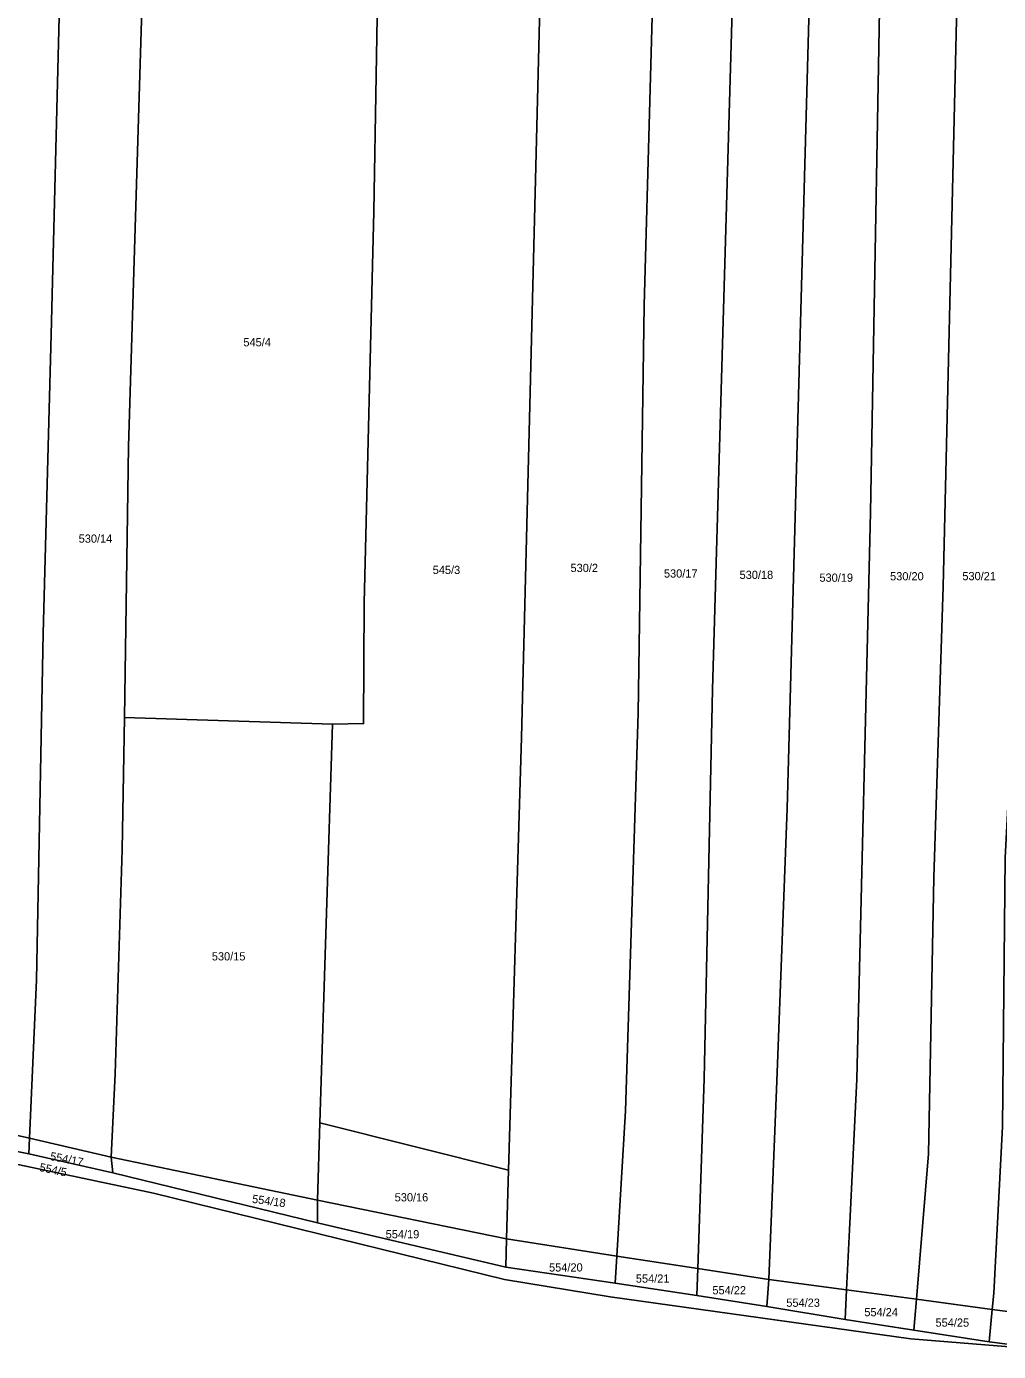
# Model space of a CAD drawing. Extents: x -747333 to -743907, y -1134120 to -1130051.
# Drawn here: x -746843.6 to -746642.5, y -1133009.1 to -1132734.9 of the extents above; entities that cross this region are included whole.
import ezdxf

# ---------------------------------------------------------------- set-up
doc = ezdxf.new("R2010")
doc.units = 0
doc.layers.add('Hranice parcel', color=7, linetype='Continuous')
doc.layers.add('Parcelní čísla', color=7, linetype='Continuous')

msp = doc.modelspace()

# ---------------------------------------------------------------- linework, layer by layer
at = {"layer": 'Hranice parcel'}
for p, q in [((-746780.29, -1132879.28), (-746823.3, -1132877.9)), ((-746782.89, -1132961.74), (-746780.29, -1132879.28)), ((-746859.24, -1132961.35), (-746843.01, -1132964.9)), ((-746783.4, -1132977.73), (-746782.89, -1132961.74)), ((-746743.9, -1132971.52), (-746782.89, -1132961.74)), ((-746843.15, -1132968.18), (-746859.32, -1132964.96)), ((-746843.15, -1132968.18), (-746843.01, -1132964.9)), ((-746843.01, -1132964.9), (-746826.09, -1132968.83)), ((-746825.76, -1132972.07), (-746843.15, -1132968.18)), ((-746825.76, -1132972.07), (-746826.09, -1132968.83)), ((-746826.09, -1132968.83), (-746783.4, -1132977.73)), ((-746783.4, -1132982.44), (-746825.76, -1132972.07)), ((-746743.9, -1132971.52), (-746744.27, -1132985.78)), ((-746783.4, -1132982.44), (-746783.4, -1132977.73)), ((-746783.4, -1132977.73), (-746744.27, -1132985.78)), ((-746744.46, -1132991.63), (-746783.4, -1132982.44)), ((-746744.46, -1132991.63), (-746744.27, -1132985.78)), ((-746744.27, -1132985.78), (-746721.44, -1132989.34)), ((-746721.78, -1132994.93), (-746721.44, -1132989.34)), ((-746721.44, -1132989.34), (-746704.71, -1132991.91)), ((-746721.78, -1132994.93), (-746744.46, -1132991.63)), ((-746704.9, -1132997.51), (-746704.71, -1132991.91)), ((-746704.71, -1132991.91), (-746690.04, -1132994.16)), ((-746704.9, -1132997.51), (-746721.78, -1132994.93)), ((-746690.41, -1132999.79), (-746690.04, -1132994.16)), ((-746690.04, -1132994.16), (-746673.93, -1132996.32)), ((-746690.41, -1132999.79), (-746704.9, -1132997.51)), ((-746674.21, -1133002.43), (-746673.93, -1132996.32)), ((-746673.93, -1132996.32), (-746659.48, -1132998.26)), ((-746674.21, -1133002.43), (-746690.41, -1132999.79)), ((-746660.01, -1133004.66), (-746659.48, -1132998.26)), ((-746659.48, -1132998.26), (-746643.78, -1133000.37)), ((-746644.4, -1133007.07), (-746643.78, -1133000.37)), ((-746643.78, -1133000.37), (-746628.03, -1133002.49)), ((-746660.01, -1133004.66), (-746674.21, -1133002.43)), ((-746644.4, -1133007.07), (-746660.01, -1133004.66)), ((-746628.31, -1133009.07), (-746644.4, -1133007.07))]:
    msp.add_line(p, q, dxfattribs=at)
for points in [[(-746643.78, -1133000.37), (-746643.47, -1132997), (-746641.69, -1132962.6), (-746641.11, -1132906.92), (-746640.39, -1132892.35), (-746638.47, -1132779.07), (-746636.9, -1132758.37), (-746635.57, -1132695.85)], [(-746659.48, -1132998.26), (-746657.01, -1132968.18), (-746655.87, -1132911.01), (-746653.95, -1132850.77), (-746651.38, -1132742.33), (-746650.38, -1132698.13)], [(-746673.93, -1132996.32), (-746673.35, -1132983.87), (-746671.78, -1132952.75), (-746668.96, -1132835.45), (-746666.57, -1132700.62)], [(-746690.04, -1132994.16), (-746688.34, -1132953.1), (-746686.22, -1132896.69), (-746681.65, -1132730.8), (-746681.2, -1132702.87)], [(-746704.71, -1132991.91), (-746703.4, -1132952.68), (-746701.64, -1132872.12), (-746696.87, -1132705.27)], [(-746721.44, -1132989.34), (-746719.64, -1132959.24), (-746717.06, -1132876.97), (-746715.78, -1132792.6), (-746713.45, -1132707.83)], [(-746736.91, -1132711.52), (-746741.19, -1132882), (-746743.9, -1132971.52)], [(-746770.75, -1132716.83), (-746771.72, -1132773.21), (-746773.72, -1132854.16), (-746773.87, -1132879.14), (-746780.29, -1132879.28)], [(-746823.3, -1132877.9), (-746822.5, -1132821.8), (-746819.55, -1132724.49)], [(-746843.01, -1132964.9), (-746841.51, -1132932.14), (-746840.15, -1132860.48), (-746838.51, -1132798.6), (-746836.72, -1132727.3)], [(-746826.09, -1132968.83), (-746825.23, -1132951.59), (-746823.81, -1132905.23), (-746823.3, -1132877.9)], [(-746929.35, -1132954.76), (-746891.82, -1132961.76), (-746852.29, -1132968.9), (-746817.33, -1132976.32), (-746744.69, -1132994.17), (-746722.86, -1132997.73), (-746660.65, -1133006.44), (-746628.31, -1133009.07)]]:
    msp.add_lwpolyline(points, dxfattribs=at)

# ---------------------------------------------------------------- texts
at = {"layer": 'Parcelní čísla'}
for s, p in [('545/4', (-746798.73, -1132801.08)), ('530/14', (-746832.81, -1132841.71)), ('545/3', (-746759.56, -1132848.19)), ('530/2', (-746731.05, -1132847.78)), ('530/17', (-746711.72, -1132848.93)), ('530/18', (-746696.07, -1132849.21)), ('530/19', (-746679.55, -1132849.79)), ('530/20', (-746664.93, -1132849.5)), ('530/21', (-746649.98, -1132849.47)), ('530/15', (-746805.26, -1132928.15)), ('530/16', (-746767.43, -1132978.01)), ('554/19', (-746769.29, -1132985.65)), ('554/20', (-746735.49, -1132992.52)), ('554/21', (-746717.53, -1132994.83)), ('554/22', (-746701.69, -1132997.24)), ('554/23', (-746686.4, -1132999.82)), ('554/24', (-746670.26, -1133001.78)), ('554/25', (-746655.53, -1133003.94))]:
    msp.add_text(s, height=1.7, dxfattribs=at).set_placement(p)
for s, rotation, p in [('554/17', 349, (-746838.842, -1132969.434)), ('554/5', 348, (-746841.036, -1132971.701)), ('554/18', 352, (-746797.008, -1132978.281))]:
    msp.add_text(s, height=1.7, rotation=rotation, dxfattribs=at).set_placement(p)

doc.saveas('drawing.dxf')
